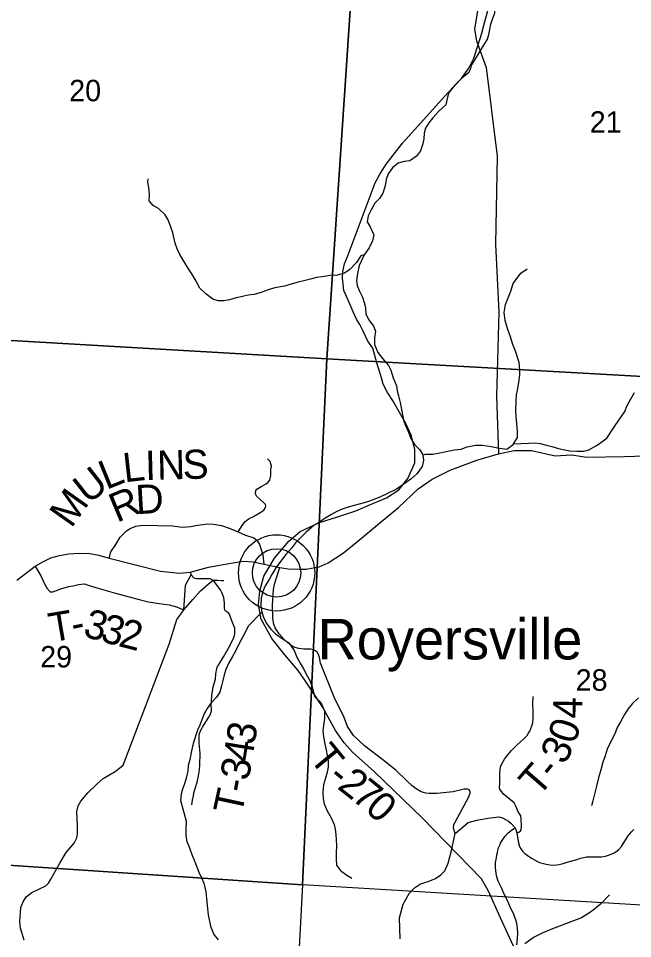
# Model space of a CAD drawing. Extents: x 0 to 82.7, y -0.2 to 22.
# Drawn here: x 7.048 to 8.246, y 15.035 to 16.831 of the extents above; entities that cross this region are included whole.
import ezdxf

# ---------------------------------------------------------------- set-up
doc = ezdxf.new("R2010")
doc.units = 0
for name, color, linetype in [('GM_X_County_Road', 7, 'Continuous'), ('GM_X_Minor_River', 7, 'Continuous'), ('GM_X_Rail_Line', 7, 'Continuous'), ('GM_X_Section', 7, 'Continuous'), ('GM_X_Section_Text', 7, 'Continuous'), ('GM_X_Township_Road', 7, 'Continuous'), ('GM_X_Township_Road_Text', 7, 'Continuous'), ('GM_X_Unincorporated', 7, 'Continuous'), ('GM_X_Unincorporated_Location', 7, 'Continuous'), ('GM_X_Unincorporated_Text', 7, 'Continuous')]:
    doc.layers.add(name, color=color, linetype=linetype)

msp = doc.modelspace()

# ---------------------------------------------------------------- linework, layer by layer
at = {"layer": 'GM_X_County_Road'}
for points in [[(7.0445, 15.7347), (7.0802, 15.762), (7.0965, 15.7711), (7.1109, 15.778), (7.1275, 15.7826), (7.1458, 15.7862), (7.1654, 15.7875), (7.1873, 15.7868), (7.2046, 15.7836), (7.2249, 15.7777), (7.3252, 15.7519), (7.3616, 15.7483), (7.383, 15.7505), (7.4183, 15.7597), (7.4514, 15.7662), (7.4865, 15.7716), (7.5065, 15.7703), (7.5269, 15.7658), (7.5578, 15.7593), (7.5743, 15.757), (7.5954, 15.7559), (7.609, 15.7559), (7.6228, 15.7586), (7.6344, 15.7605), (7.6523, 15.7686), (7.6823, 15.7882), (7.7174, 15.8168), (7.7521, 15.8459), (7.7894, 15.8764), (7.8276, 15.913), (7.855, 15.9318), (7.89, 15.9491), (7.9421, 15.9689), (7.9845, 15.981), (8.0154, 15.9878), (8.0488, 15.988), (8.0954, 15.9771), (8.1269, 15.9793), (8.1571, 15.9748), (8.2304, 15.9762), (8.2915, 15.9777)], [(7.383, 15.7505), (7.3848, 15.7452), (7.3898, 15.7395), (7.3951, 15.7376), (7.4031, 15.7376), (7.4141, 15.7382), (7.4209, 15.7382), (7.4275, 15.7347), (7.4366, 15.7345), (7.4431, 15.734), (7.4486, 15.734)]]:
    msp.add_lwpolyline(points, dxfattribs=at)
msp.add_lwpolyline([(7.9374, 14.1), (8.5415, 14.1), (8.6007, 15.0799), (7.6018, 15.1403), (7.5478, 14.1251)], close=True, dxfattribs=at)
at = {"layer": 'GM_X_Minor_River'}
for points in [[(7.9308, 16.7373), (7.9558, 16.779), (7.9631, 16.7903), (7.9654, 16.7998), (7.9678, 16.8096), (7.9697, 16.8199), (7.9736, 16.8312), (7.9774, 16.8414), (7.9779, 16.8509), (7.9772, 16.8612), (7.9773, 16.871), (7.9789, 16.882), (7.9785, 16.8919), (7.979, 16.9021), (7.9806, 16.9131), (7.9837, 16.9245), (7.9932, 16.9354), (8.0028, 16.9445), (8.0123, 16.9508), (8.0331, 16.9675), (8.0286, 16.9598)], [(7.9308, 16.7373), (7.9305, 16.7354), (7.9264, 16.7252), (7.9131, 16.7142), (7.8992, 16.7009), (7.8874, 16.6865), (7.8852, 16.677), (7.8818, 16.6622), (7.8681, 16.6497), (7.8564, 16.6368), (7.8485, 16.6269), (7.8424, 16.617), (7.8394, 16.6072), (7.8386, 16.5958), (7.8371, 16.5859), (7.8322, 16.5727), (7.8247, 16.5624), (7.8118, 16.5533), (7.8005, 16.5514), (7.7887, 16.5484), (7.7778, 16.5396), (7.7695, 16.5279), (7.7653, 16.5169), (7.7634, 16.504), (7.7589, 16.49), (7.7521, 16.4797), (7.743, 16.4702), (7.7354, 16.4558), (7.7301, 16.4459), (7.7282, 16.4342), (7.7339, 16.4243), (7.7415, 16.4084), (7.7388, 16.397), (7.732, 16.3834), (7.7226, 16.3693), (7.7169, 16.3587), (7.7127, 16.3488), (7.7093, 16.3329), (7.7074, 16.3193), (7.7086, 16.3094), (7.7127, 16.2999), (7.7191, 16.2867), (7.7225, 16.2764), (7.7248, 16.2666), (7.7255, 16.254), (7.7312, 16.243), (7.7403, 16.2305), (7.7444, 16.2207), (7.7426, 16.2078), (7.7425, 16.1945), (7.749, 16.179), (7.758, 16.1672), (7.7698, 16.1539), (7.7743, 16.1445), (7.7792, 16.1297), (7.7852, 16.1141), (7.7871, 16.1043), (7.7894, 16.0944), (7.7924, 16.0815), (7.7954, 16.0675), (7.7977, 16.0538), (7.8, 16.0444), (7.8038, 16.0349), (7.8087, 16.0235), (7.8136, 16.011), (7.8215, 15.9989), (7.831, 15.989), (7.837, 15.9792), (7.8381, 15.9682), (7.8355, 15.9568), (7.8253, 15.9424), (7.8136, 15.9317), (7.8026, 15.9238), (7.7852, 15.9124), (7.7667, 15.9029), (7.7542, 15.8972), (7.7432, 15.8926), (7.7327, 15.8888), (7.7224, 15.8854), (7.7028, 15.8801), (7.6911, 15.877), (7.6797, 15.8732), (7.6691, 15.8687), (7.6586, 15.863), (7.6465, 15.8554), (7.6355, 15.8478), (7.6245, 15.8417), (7.6094, 15.8285), (7.5992, 15.8186), (7.5886, 15.8076), (7.5807, 15.797), (7.5693, 15.7848), (7.5591, 15.7712), (7.5497, 15.7586), (7.5421, 15.7457), (7.5372, 15.7362), (7.5292, 15.7237), (7.524, 15.7112), (7.5217, 15.6987), (7.5209, 15.685)], [(7.334, 16.4475), (7.3211, 16.4599), (7.3109, 16.4656), (7.303, 16.4751), (7.3034, 16.4865), (7.3023, 16.5009), (7.3004, 16.5115), (7.3008, 16.518)], [(7.7226, 16.3693), (7.7157, 16.3674), (7.7074, 16.3549), (7.6946, 16.3409), (7.684, 16.3337), (7.67, 16.3302), (7.656, 16.3295), (7.6401, 16.3268), (7.6292, 16.3253), (7.6175, 16.3222), (7.6072, 16.3196), (7.5936, 16.3165), (7.5819, 16.3131), (7.5668, 16.3086), (7.5483, 16.3051), (7.535, 16.301), (7.5214, 16.296), (7.5071, 16.2922), (7.4957, 16.2907), (7.4851, 16.2884), (7.4727, 16.2857), (7.4598, 16.2816), (7.4485, 16.28), (7.4375, 16.2796), (7.4273, 16.2831), (7.4137, 16.2937), (7.402, 16.3043), (7.3944, 16.3179), (7.3861, 16.3323), (7.3793, 16.3422), (7.3721, 16.3539), (7.3627, 16.3699), (7.3574, 16.3812), (7.3536, 16.3926), (7.3491, 16.4127), (7.3445, 16.4252), (7.3396, 16.4381), (7.334, 16.4475)], [(7.837, 15.9792), (7.8423, 15.9807), (7.8563, 15.9807), (7.8703, 15.983), (7.8824, 15.9856), (7.899, 15.989), (7.9115, 15.9906), (7.9236, 15.9947), (7.9394, 15.9978), (7.9531, 15.9978), (7.9704, 15.9952), (7.9867, 15.9925), (8.0007, 15.9902), (8.0132, 15.9993), (8.0215, 16.0134), (8.0219, 16.0244), (8.0203, 16.0407), (8.0192, 16.054), (8.0185, 16.0653), (8.0188, 16.0839), (8.02, 16.0961), (8.0215, 16.1055), (8.0241, 16.1207), (8.026, 16.1351), (8.0264, 16.1446), (8.0249, 16.1594), (8.0177, 16.1814), (8.0128, 16.1943), (8.0072, 16.2113), (8.0034, 16.2216), (8.0004, 16.2322), (7.9977, 16.2417), (7.9958, 16.2572), (7.9985, 16.2724), (8.0045, 16.2891), (8.0087, 16.2986), (8.0132, 16.3134), (8.0284, 16.3339), (8.0408, 16.3422)], [(8.0132, 15.9993), (8.0135, 16.0009), (8.029, 16.0013), (8.043, 16.002), (8.0547, 16.0024), (8.0661, 16.0013), (8.0782, 15.9982), (8.0888, 15.9952), (8.1016, 15.9918), (8.1137, 15.9888), (8.1239, 15.9873), (8.1375, 15.9861), (8.1511, 15.9865), (8.161, 15.9892), (8.1768, 15.9983), (8.1957, 16.012), (8.212, 16.0362), (8.2241, 16.0537), (8.2309, 16.0639), (8.2358, 16.0753), (8.2422, 16.0871), (8.2502, 16.1011)], [(7.5209, 15.685), (7.5228, 15.6725), (7.5258, 15.6623), (7.5315, 15.6498), (7.5402, 15.6392), (7.5496, 15.6297), (7.564, 15.6198), (7.5753, 15.6123), (7.5859, 15.5975), (7.5912, 15.5842), (7.5973, 15.5725), (7.6041, 15.5615), (7.6112, 15.5482), (7.6161, 15.5387), (7.6211, 15.5266), (7.6256, 15.5076), (7.6377, 15.4962), (7.6452, 15.4796), (7.6449, 15.4644), (7.643, 15.4507), (7.6418, 15.4405), (7.643, 15.4287), (7.6456, 15.4155), (7.6483, 15.4026), (7.6505, 15.3927), (7.652, 15.3817), (7.6524, 15.3696), (7.6505, 15.3597), (7.6471, 15.3483), (7.6429, 15.3354), (7.6418, 15.3207), (7.6422, 15.3081), (7.6441, 15.2979), (7.6505, 15.2846), (7.6577, 15.271), (7.6637, 15.2581), (7.6667, 15.2448), (7.6679, 15.2289), (7.6682, 15.2149), (7.6679, 15.2035), (7.6675, 15.1906), (7.6686, 15.1784), (7.6762, 15.1678), (7.6883, 15.1591), (7.6981, 15.1534)], [(7.5228, 15.6725), (7.4963, 15.6452), (7.4892, 15.6315), (7.4793, 15.6126), (7.471, 15.5959), (7.4653, 15.5856), (7.4585, 15.5731), (7.4525, 15.5602), (7.4491, 15.5496), (7.4468, 15.539), (7.4441, 15.5287), (7.4407, 15.5162), (7.4343, 15.5064), (7.4241, 15.495), (7.4162, 15.4843), (7.4097, 15.4722), (7.4056, 15.4623), (7.4014, 15.4517), (7.3973, 15.4419), (7.3886, 15.4157), (7.3855, 15.4013), (7.3821, 15.3846), (7.3791, 15.3728), (7.378, 15.3622), (7.3753, 15.3485), (7.3715, 15.3375), (7.3681, 15.3269), (7.3651, 15.3167), (7.364, 15.3045), (7.3685, 15.2882), (7.3753, 15.264), (7.3745, 15.248), (7.3745, 15.2355), (7.376, 15.2249), (7.3817, 15.212), (7.3862, 15.1991), (7.3908, 15.1885), (7.3946, 15.1783), (7.3995, 15.1646), (7.4051, 15.1536), (7.4093, 15.143), (7.4131, 15.1267), (7.415, 15.1134), (7.4161, 15.0998), (7.418, 15.0812), (7.4225, 15.0596), (7.4293, 15.0433), (7.4376, 15.0327)], [(8.258, 15.5053), (8.2451, 15.4936), (8.2372, 15.4829), (8.2304, 15.4723), (8.2228, 15.4583), (8.2156, 15.4461), (8.2122, 15.4363), (8.2054, 15.4222), (8.1964, 15.4048), (8.193, 15.3915), (8.188, 15.3794), (8.1843, 15.3646), (8.1797, 15.3487), (8.1756, 15.3327), (8.1721, 15.3172), (8.1687, 15.3043), (8.1661, 15.294)], [(8.2014, 15.1204), (8.1836, 15.1021), (8.1661, 15.0881), (8.1468, 15.0755), (8.126, 15.068), (8.1085, 15.0615), (8.09, 15.0543), (8.0699, 15.046), (8.0528, 15.0376), (8.0358, 15.0251)]]:
    msp.add_lwpolyline(points, dxfattribs=at)
at = {"layer": 'GM_X_Rail_Line'}
msp.add_lwpolyline([(8.0139, 15.0201), (8.0019, 15.0459), (7.9885, 15.0754), (7.9643, 15.1293), (7.9515, 15.1518), (7.8356, 15.2709), (7.7423, 15.3603), (7.6993, 15.399), (7.6832, 15.4175), (7.6663, 15.4412), (7.641, 15.4874), (7.621, 15.5183), (7.6064, 15.5397), (7.5935, 15.5582), (7.5678, 15.5888), (7.5421, 15.621), (7.5217, 15.6586), (7.5163, 15.6869), (7.5187, 15.7135), (7.5268, 15.7425), (7.5477, 15.7778), (7.5753, 15.8106), (7.5975, 15.8295), (7.6354, 15.8471), (7.6683, 15.8579), (7.7063, 15.8698), (7.7395, 15.8845), (7.7661, 15.8953), (7.7898, 15.911), (7.8079, 15.9329), (7.8212, 15.9638), (7.8212, 15.9895), (7.8147, 16.0161), (7.8035, 16.0402), (7.7855, 16.0726), (7.7793, 16.084), (7.768, 16.101), (7.7595, 16.1171), (7.7562, 16.1293), (7.7474, 16.1591), (7.739, 16.1871), (7.7295, 16.2011), (7.7199, 16.2219), (7.7138, 16.2338), (7.7075, 16.2441), (7.701, 16.2583), (7.6959, 16.2707), (7.6828, 16.3001), (7.6816, 16.3122), (7.6804, 16.3243), (7.6808, 16.3373), (7.684, 16.3517), (7.6909, 16.3693), (7.7439, 16.5102), (7.752, 16.5255), (7.7651, 16.5464), (7.797, 16.5872), (7.8855, 16.6856), (7.9121, 16.7137), (7.9266, 16.7338), (7.9362, 16.7532), (7.9531, 16.8063), (7.9531, 16.8079), (7.9732, 16.8827)], dxfattribs=at)
at = {"layer": 'GM_X_Section'}
msp.add_lwpolyline([(6.7452, 17.2376), (7.7171, 17.1775), (7.6497, 16.1665), (6.6409, 16.2254), (6.6789, 16.7875)], dxfattribs=at)
for points in [[(7.7171, 17.1775), (8.7418, 17.1109), (8.6725, 16.1095), (7.6497, 16.1665)], [(6.6409, 16.2254), (7.6497, 16.1665), (7.6018, 15.1403), (6.5889, 15.2079)], [(7.6497, 16.1665), (8.6725, 16.1095), (8.6007, 15.0799), (7.6018, 15.1403)], [(7.6018, 15.1403), (7.5478, 14.1251), (6.5375, 14.1911), (6.5889, 15.2079)]]:
    msp.add_lwpolyline(points, close=True, dxfattribs=at)
at = {"layer": 'GM_X_Township_Road'}
for points in [[(8.2267, 17.0286), (8.1998, 17.0048), (8.1766, 16.9883), (8.1476, 16.966), (8.1244, 16.9467), (8.106, 16.937), (8.0866, 16.937), (8.0479, 16.9399), (8.0295, 16.9409), (8.0198, 16.9515), (8.0073, 16.9622), (8.0034, 16.9738), (7.9947, 16.9825), (7.985, 16.9815), (7.9743, 16.966), (7.9637, 16.9515), (7.9559, 16.9428), (7.9502, 16.9244), (7.9492, 16.8964), (7.9482, 16.8731), (7.9434, 16.846), (7.9405, 16.8257), (7.9403, 16.8247)], [(7.9403, 16.8247), (7.9391, 16.8185), (7.9376, 16.8102), (7.9414, 16.787), (7.9604, 16.7349), (7.982, 16.5619), (7.9789, 16.3905), (7.9851, 16.2576), (7.9804, 16.0939), (7.9845, 15.981)], [(7.4763, 15.8291), (7.4854, 15.8435), (7.49, 15.8491), (7.4979, 15.8548), (7.5066, 15.8586), (7.5209, 15.8673), (7.5268, 15.871), (7.53, 15.8766), (7.5305, 15.8794), (7.5296, 15.8825), (7.5268, 15.8853), (7.5121, 15.8988), (7.51, 15.9041), (7.5107, 15.9097), (7.5131, 15.9123), (7.5226, 15.9183), (7.5312, 15.9227), (7.5352, 15.9258), (7.538, 15.9295), (7.5403, 15.939), (7.5403, 15.9509), (7.5415, 15.9572), (7.5391, 15.9661), (7.5335, 15.9714)], [(7.2249, 15.7777), (7.2278, 15.7898), (7.2376, 15.8045), (7.2461, 15.8188), (7.2585, 15.8309), (7.2657, 15.8358), (7.2771, 15.8401), (7.2905, 15.8417), (7.3484, 15.8406), (7.3673, 15.8381), (7.3844, 15.8394), (7.393, 15.8414), (7.4167, 15.8447), (7.4281, 15.8438), (7.444, 15.8414), (7.4592, 15.8361), (7.4763, 15.8291), (7.491, 15.8226), (7.5069, 15.8173), (7.5131, 15.8125), (7.518, 15.8042), (7.5245, 15.7842), (7.5269, 15.7658)], [(7.0802, 15.762), (7.092, 15.7417), (7.0988, 15.7274), (7.1037, 15.7182), (7.1096, 15.712), (7.1148, 15.712), (7.1302, 15.7179), (7.1462, 15.7222), (7.1543, 15.7235), (7.1651, 15.7264), (7.1765, 15.7274), (7.1857, 15.7241), (7.2053, 15.7186), (7.2373, 15.7091), (7.283, 15.697), (7.3013, 15.6926), (7.3224, 15.6894), (7.3419, 15.6864), (7.356, 15.6827), (7.3702, 15.6766), (7.3881, 15.6972), (7.4033, 15.7138), (7.4189, 15.7275), (7.4275, 15.7347)], [(7.544, 15.6601), (7.5435, 15.6861), (7.5453, 15.7156), (7.5468, 15.7245), (7.5501, 15.7356), (7.5578, 15.7593)], [(7.059, 15.0318), (7.0515, 15.0556), (7.0507, 15.0686), (7.0526, 15.096), (7.0569, 15.1068), (7.0626, 15.1169), (7.0735, 15.1248), (7.1012, 15.1384), (7.1064, 15.1431), (7.1111, 15.1509), (7.1286, 15.1822), (7.1405, 15.2031), (7.1564, 15.2211), (7.1618, 15.2316), (7.1629, 15.2395), (7.1629, 15.2554), (7.1618, 15.2834), (7.1643, 15.2942), (7.1695, 15.3031), (7.1829, 15.3193), (7.2011, 15.337), (7.2131, 15.3478), (7.2239, 15.3541), (7.2365, 15.3615), (7.252, 15.3735), (7.342, 15.61), (7.3565, 15.6579), (7.3648, 15.6683), (7.3702, 15.6766), (7.374, 15.7245), (7.3755, 15.7289), (7.3848, 15.7452)], [(7.3861, 15.2961), (7.3872, 15.3056), (7.389, 15.3137), (7.3901, 15.3195), (7.3964, 15.3403), (7.3992, 15.3528), (7.4012, 15.3647), (7.4014, 15.3734), (7.4021, 15.3971), (7.4006, 15.4166), (7.4001, 15.4301), (7.401, 15.4355), (7.4029, 15.4403), (7.4071, 15.4477), (7.419, 15.4672), (7.4218, 15.4718), (7.4244, 15.4796), (7.4244, 15.4835), (7.4238, 15.4885), (7.4246, 15.4982), (7.4252, 15.5091), (7.4279, 15.5266), (7.4321, 15.5414), (7.433, 15.5518), (7.4348, 15.5621), (7.4362, 15.5661), (7.4379, 15.5685), (7.4479, 15.585), (7.4601, 15.6068), (7.4689, 15.6239), (7.4702, 15.6304), (7.4697, 15.6409), (7.4644, 15.6551), (7.4596, 15.6682), (7.4567, 15.6714), (7.4514, 15.6749), (7.4497, 15.6803), (7.4496, 15.6895), (7.4482, 15.7008), (7.4472, 15.7044), (7.4449, 15.7104), (7.4417, 15.7159), (7.4275, 15.7347)], [(7.8997, 15.2403), (7.8967, 15.2508), (7.8977, 15.258), (7.8998, 15.2626), (7.9055, 15.2723), (7.9258, 15.3103), (7.9295, 15.3191), (7.9294, 15.3228), (7.9271, 15.3255), (7.924, 15.3267), (7.9178, 15.3268), (7.8958, 15.3215), (7.8643, 15.3183), (7.8494, 15.318), (7.8427, 15.3192), (7.8335, 15.3215), (7.8239, 15.3271), (7.8159, 15.3334), (7.8054, 15.3433), (7.7839, 15.3638), (7.7586, 15.3842), (7.7229, 15.4115), (7.7013, 15.4317), (7.69, 15.449), (7.6832, 15.4665), (7.6636, 15.5066), (7.6371, 15.5729), (7.6349, 15.5837), (7.6332, 15.5899), (7.6304, 15.5943), (7.6267, 15.5969), (7.623, 15.599), (7.6181, 15.5998), (7.6045, 15.6001), (7.5947, 15.6015), (7.585, 15.604), (7.5776, 15.6089), (7.566, 15.6186), (7.5563, 15.6299), (7.549, 15.6415), (7.5459, 15.6487), (7.544, 15.6601)], [(8.0201, 15.2413), (8.0241, 15.2429), (8.0274, 15.2454), (8.0285, 15.2475), (8.0293, 15.2539), (8.0293, 15.2591), (8.0285, 15.2644), (8.0287, 15.2698), (8.028, 15.2749), (8.0264, 15.2782), (8.0228, 15.2824), (8.0183, 15.2933), (8.0149, 15.3), (7.9944, 15.3171), (7.9869, 15.3267), (7.9865, 15.3299), (7.987, 15.3378), (7.9873, 15.3469), (7.9874, 15.3572), (7.9881, 15.3646), (7.9886, 15.3701), (7.9903, 15.3747), (7.9965, 15.3855), (8.0026, 15.3936), (8.0097, 15.4024), (8.0203, 15.4124), (8.0349, 15.4256), (8.0402, 15.4315), (8.0434, 15.436), (8.0458, 15.4402), (8.0477, 15.445), (8.0494, 15.4502), (8.0513, 15.4572), (8.0519, 15.4649), (8.052, 15.4729), (8.0519, 15.4792), (8.0518, 15.493), (8.0521, 15.5079)], [(7.7927, 15.0349), (7.7915, 15.0759), (7.7982, 15.1023), (7.8103, 15.1232), (7.8207, 15.1345), (7.8325, 15.142), (7.8472, 15.1466), (7.8617, 15.1526), (7.872, 15.1597), (7.8801, 15.1675), (7.8862, 15.1824), (7.8925, 15.207), (7.8997, 15.2403), (7.9251, 15.2615), (7.9424, 15.266), (7.9643, 15.2704), (7.9852, 15.2727), (7.9923, 15.271), (8.0041, 15.2641), (8.0093, 15.2599), (8.017, 15.2512), (8.0193, 15.2461), (8.0201, 15.2413), (8.0222, 15.2291), (8.0239, 15.222), (8.0257, 15.215), (8.0282, 15.2103), (8.0314, 15.2056), (8.0357, 15.2014), (8.0402, 15.1978), (8.0451, 15.1946), (8.0504, 15.1913), (8.0545, 15.1891), (8.0608, 15.1857), (8.0648, 15.1836), (8.0773, 15.1802), (8.0848, 15.1791), (8.0925, 15.1786), (8.098, 15.1789), (8.1027, 15.1795), (8.1109, 15.1818), (8.1206, 15.1848), (8.138, 15.1898), (8.1444, 15.1918), (8.1513, 15.1937), (8.1563, 15.1945), (8.161, 15.1948), (8.1733, 15.1947), (8.1855, 15.1947), (8.1932, 15.1959), (8.2013, 15.1985), (8.2091, 15.202), (8.2158, 15.2055), (8.2195, 15.2089), (8.2244, 15.2146), (8.2329, 15.2283), (8.2374, 15.2354), (8.2443, 15.2434), (8.2485, 15.2481)], [(8.0201, 15.0229), (8.0214, 15.0353), (8.0222, 15.0447), (8.0215, 15.0552), (8.0205, 15.0644), (8.0185, 15.0716), (8.016, 15.0783), (8.0142, 15.0829), (8.0089, 15.0942), (8.002, 15.1095), (7.9951, 15.1233), (7.9908, 15.1327), (7.9842, 15.1472), (7.9813, 15.1554), (7.9797, 15.1623), (7.9791, 15.1681), (7.9786, 15.174), (7.9786, 15.1779), (7.979, 15.1839), (7.9805, 15.1928), (7.9813, 15.1989), (7.9823, 15.2034), (7.9841, 15.2107), (7.9862, 15.2164), (7.9886, 15.2211), (7.9905, 15.2244), (7.9928, 15.2287), (7.9954, 15.2324), (7.9974, 15.2352), (8.0025, 15.2407), (8.0064, 15.2441), (8.01, 15.2466), (8.017, 15.2512)]]:
    msp.add_lwpolyline(points, dxfattribs=at)
at = {"layer": 'GM_X_Unincorporated'}
for radius in [0.0744, 0.0472]:
    msp.add_circle((7.5515, 15.7488), radius, dxfattribs=at)
at = {"layer": 'GM_X_Unincorporated_Location'}
msp.add_line((7.5515, 15.7488), (7.5515, 15.7488), dxfattribs=at)

# ---------------------------------------------------------------- texts
at = {"layer": 'GM_X_Section_Text'}
for s, p in [('20', (7.1467, 16.6693)), ('21', (8.1626, 16.6079)), ('29', (7.0901, 15.5643)), ('28', (8.1351, 15.5189))]:
    msp.add_text(s, height=0.04186, rotation=0, dxfattribs=at).set_placement(p)
at = {"layer": 'GM_X_Township_Road_Text'}
for s, rotation, p in [('L', 6.3404, (7.2546, 15.9255)), ('I', 1.4637, (7.2955, 15.9301)), ('N', 1.3698, (7.3188, 15.9307)), ('S', 1.3686, (7.3688, 15.9319)), ('L', 22.1161, (7.2192, 15.9105)), ('U', 38.2069, (7.1835, 15.8817)), ('M', 54.6771, (7.1509, 15.8345)), ('R', 22.7222, (7.2398, 15.8464)), ('D', 3.368, (7.2779, 15.8633)), ('T', 9.6497, (7.1118, 15.6133)), ('3', 344.1207, (7.1715, 15.6258)), ('3', 344.2848, (7.2053, 15.6162)), ('-', 11.6683, (7.1558, 15.6208)), ('2', 345.8424, (7.2407, 15.6063)), ('4', 88.8056, (8.1474, 15.464)), ('0', 72.0645, (8.1336, 15.4129)), ('3', 81.0166, (7.5084, 15.4117)), ('3', 62.8739, (8.1139, 15.3726)), ('4', 80.8357, (7.5028, 15.3769)), ('T', 309.2829, (7.6134, 15.3866)), ('3', 80.115, (7.4967, 15.3417)), ('T', 48.938, (8.0626, 15.3101)), ('-', 50.337, (8.0915, 15.3433)), ('-', 320.4799, (7.6488, 15.3451)), ('2', 321.8, (7.6679, 15.3294)), ('-', 79.3361, (7.4922, 15.3179)), ('7', 320.9607, (7.6952, 15.3079)), ('T', 77.7924, (7.4829, 15.2747)), ('0', 317.1494, (7.7217, 15.2865))]:
    msp.add_text(s, height=0.0568, rotation=rotation, dxfattribs=at).set_placement(p)
at = {"layer": 'GM_X_Unincorporated_Text'}
msp.add_text('Royersville', height=0.078977, rotation=0, dxfattribs=at).set_placement((7.6317, 15.58))

doc.saveas('drawing.dxf')
